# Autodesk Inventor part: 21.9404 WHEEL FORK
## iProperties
Created: 2010-10
Part Number: 21.9404 WHEEL FORK
Document SubType Name: Modeling
Designer: Administrator
Density: 7.85 g/cm^3
Material: Steel
Mass: 215.029 g
Surface Area: 236.712 cm^2
Volume: 27.3923 cm^3
Author: Administrator
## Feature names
1. Base1
